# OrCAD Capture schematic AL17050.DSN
size Custom; title: AL17050, UNIVERSAL HIGH VOLTAGE STEP DOWN CONVERTER; rev: 1.2; note: DS40584 Rev. 2 - 2
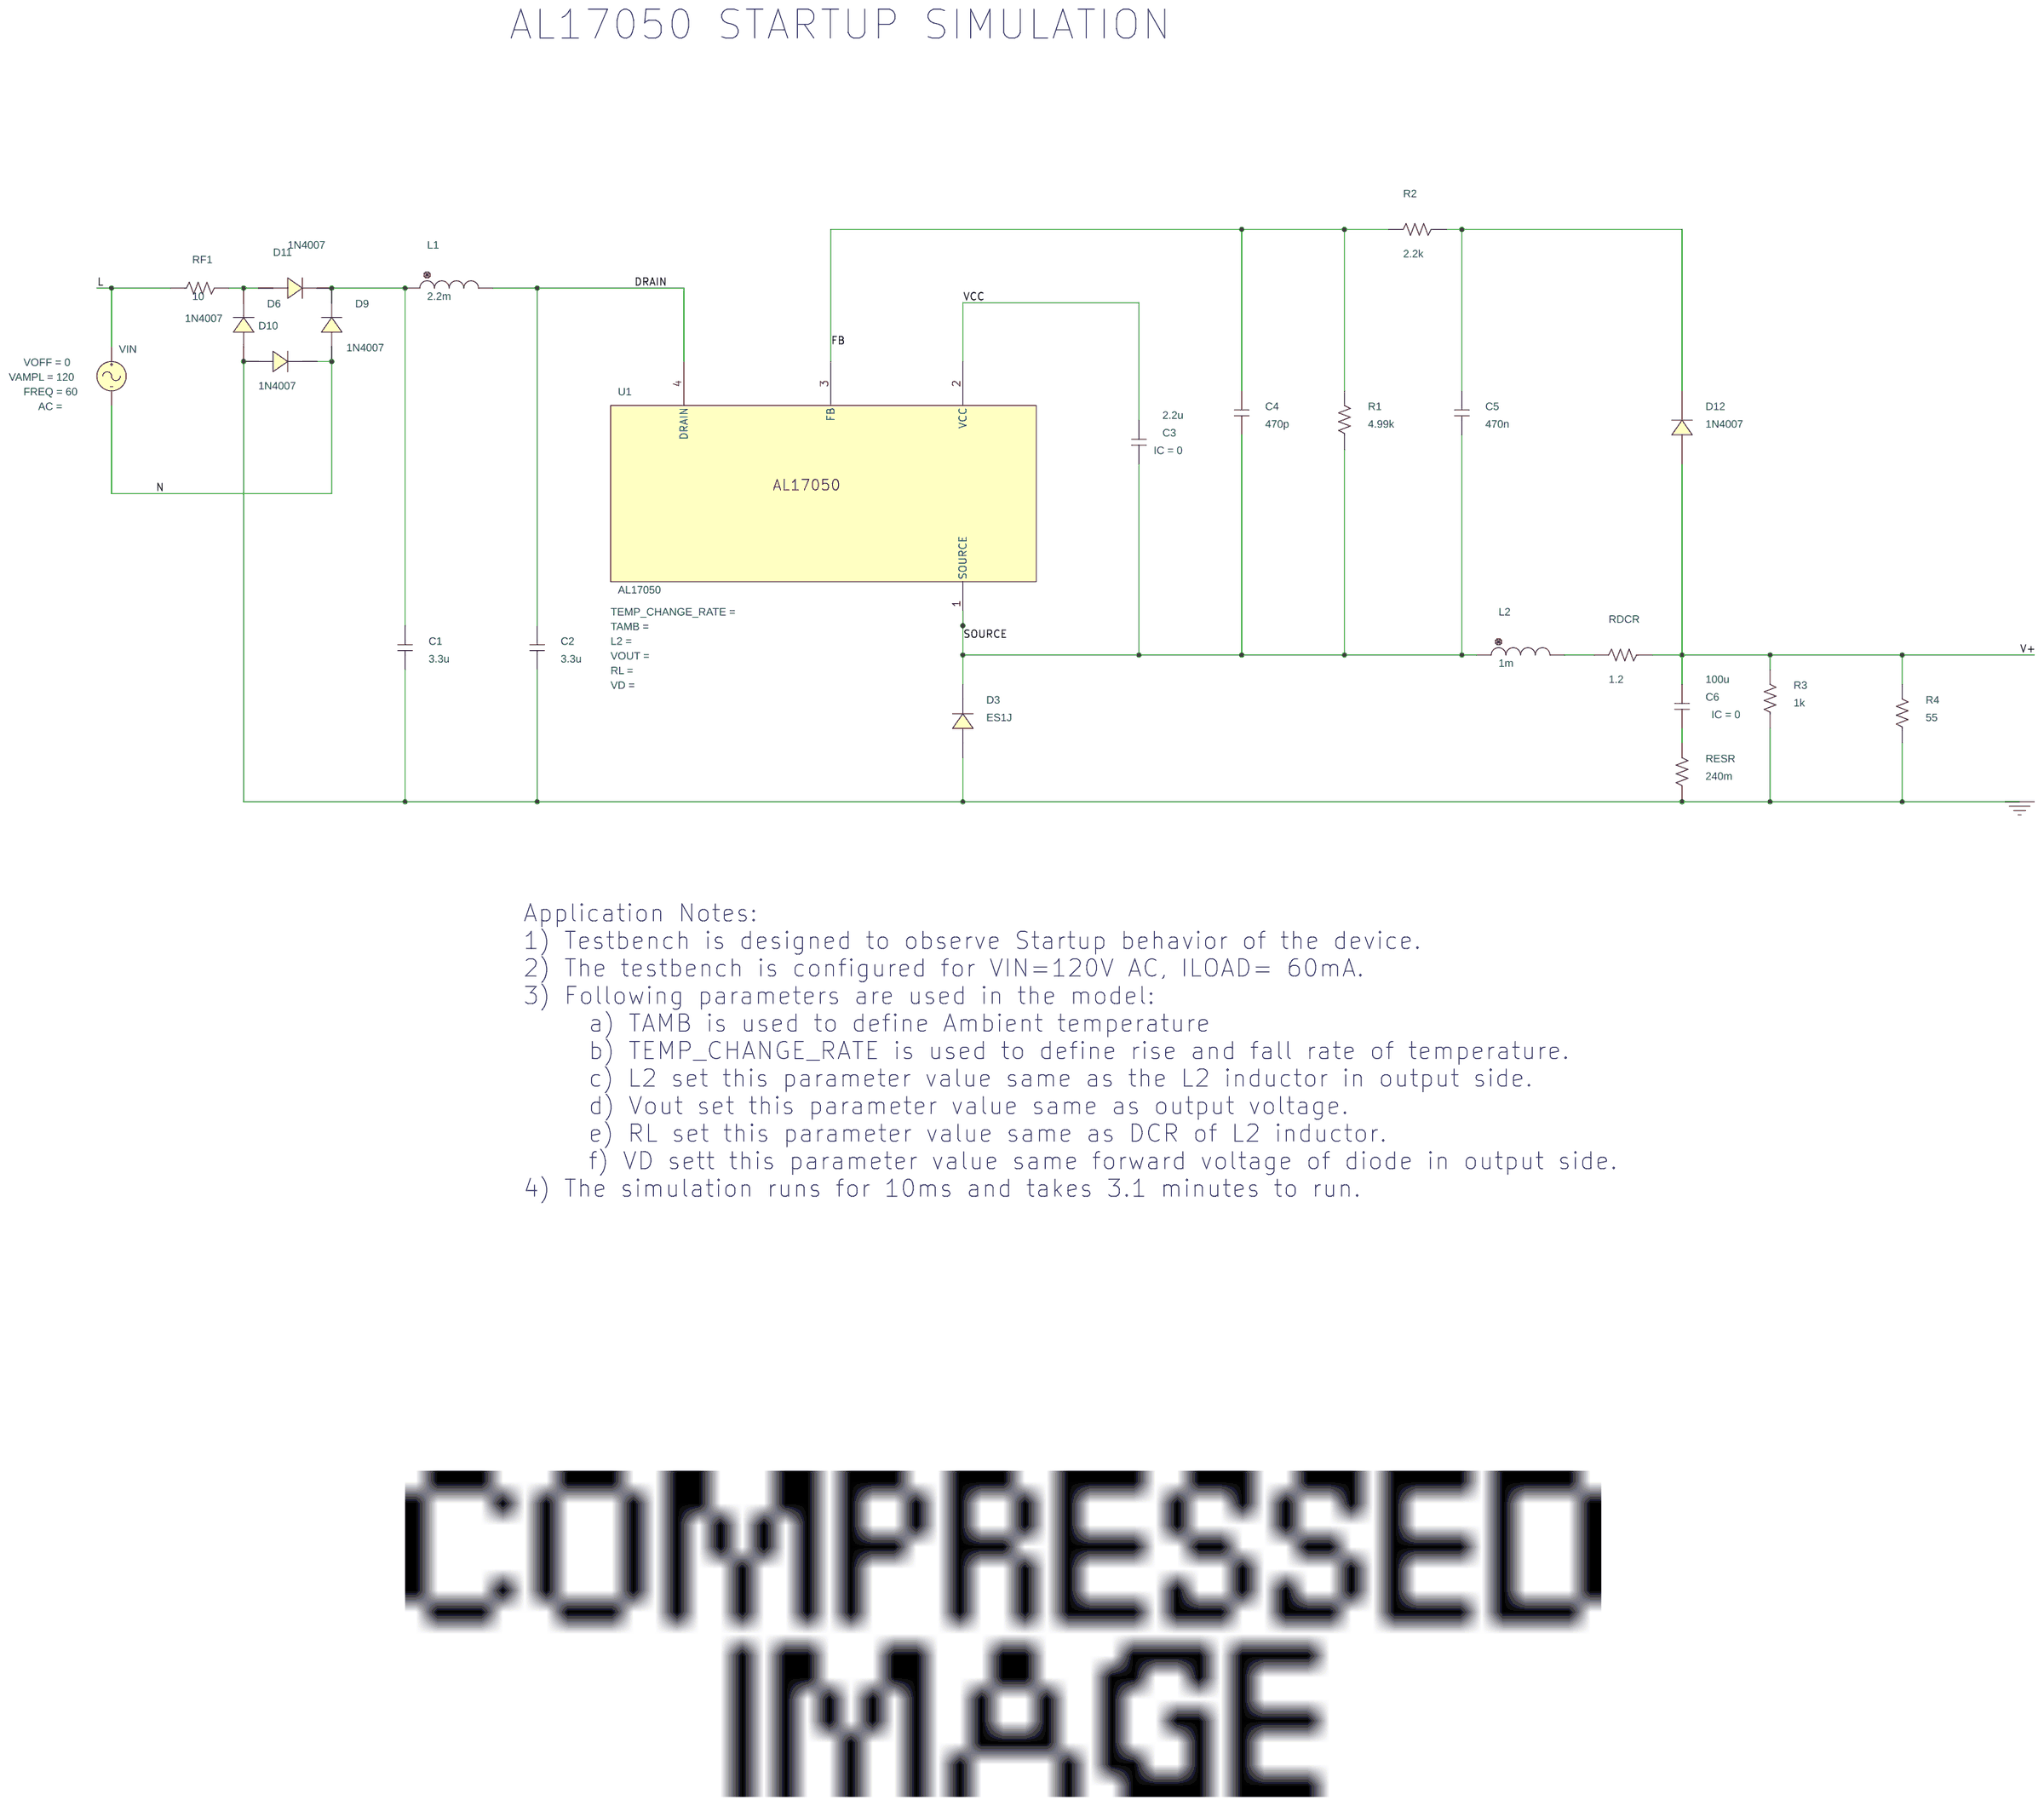
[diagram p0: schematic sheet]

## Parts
C1  3.3u  [RAD/CK05]
C2  3.3u  [RAD/CK05]
C3  2.2u  [RAD/CK05]
C4  470p  [RAD/CK05]
C5  470n  [RAD/CK05]
C6  100u  [RAD/CK05]
D3  ES1J
D6  1N4007
D9  1N4007
D10  1N4007
D11  1N4007
D12  1N4007
L1  2.2m  [DISC/.350x.175/LS.200x.100/.034]
L2  1m  [DISC/.350x.175/LS.200x.100/.034]
R1  4.99k  [AX/RC05]
R2  2.2k  [AX/RC05]
R3  1k  [AX/RC05]
R4  55  [AX/RC05]
RDCR  1.2  [AX/RC05]
RESR  240m  [AX/RC05]
RF1  10  [AX/RC05]
U1  AL17050
VIN  VSIN

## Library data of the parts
C1 C2 C4 C5 = C
C3 C6 = C: IC: 0
D3 = ES1J
D6 D9-D12 = S1MSWFQ
L1 L2 = L
R1-R4 RDCR RESR RF1 = R
U1 = AL17050
VIN = VSIN: FREQ: 60; VAMPL: 120; VOFF: 0

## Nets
VCC: C3.1 U1.2(VCC)
0: C1.1 C2.1 D3.1 D6.1 D10.1 R3.1 R4.1 RESR.1
DRAIN: C2.2 L1.2 U1.4(DRAIN)
FB: C4.2 R1.2 R2.2 U1.3(FB)
L: RF1.1 VIN.1(+)
N: D9.1 D10.2 VIN.2(-)
SOURCE: C3.2 C4.1 C5.1 D3.2 L2.1 R1.1 U1.1(SOURCE)
V+: C6.1 D12.1 R3.2 R4.2 RDCR.1
N726149: D6.2 D11.1 RF1.2
N726223: C1.2 D9.2 D11.2 L1.1
N726459: C5.2 D12.2 R2.1
N726475: L2.2 RDCR.2
N726663: C6.2 RESR.2

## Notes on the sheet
- AL17050 STARTUP SIMULATION
- Application Notes:
  1) Testbench is designed to observe Startup behavior of the device.
  2) The testbench is configured for VIN=120V AC, ILOAD= 60mA.
  3) Following parameters are used in the model:
       a) TAMB is used to define Ambient temperature
       b) TEMP_CHANGE_RATE is used to define rise and fall rate of temperature.
       c) L2 set this parameter value same as the L2 inductor in output side.
       d) Vout set this parameter value same as output voltage.
       e) RL set this parameter value same as DCR of L2 inductor.
       f) VD sett this parameter value same forward voltage of diode in output side.
  4) The simulation runs for 10ms and takes 3.1 minutes to run.
